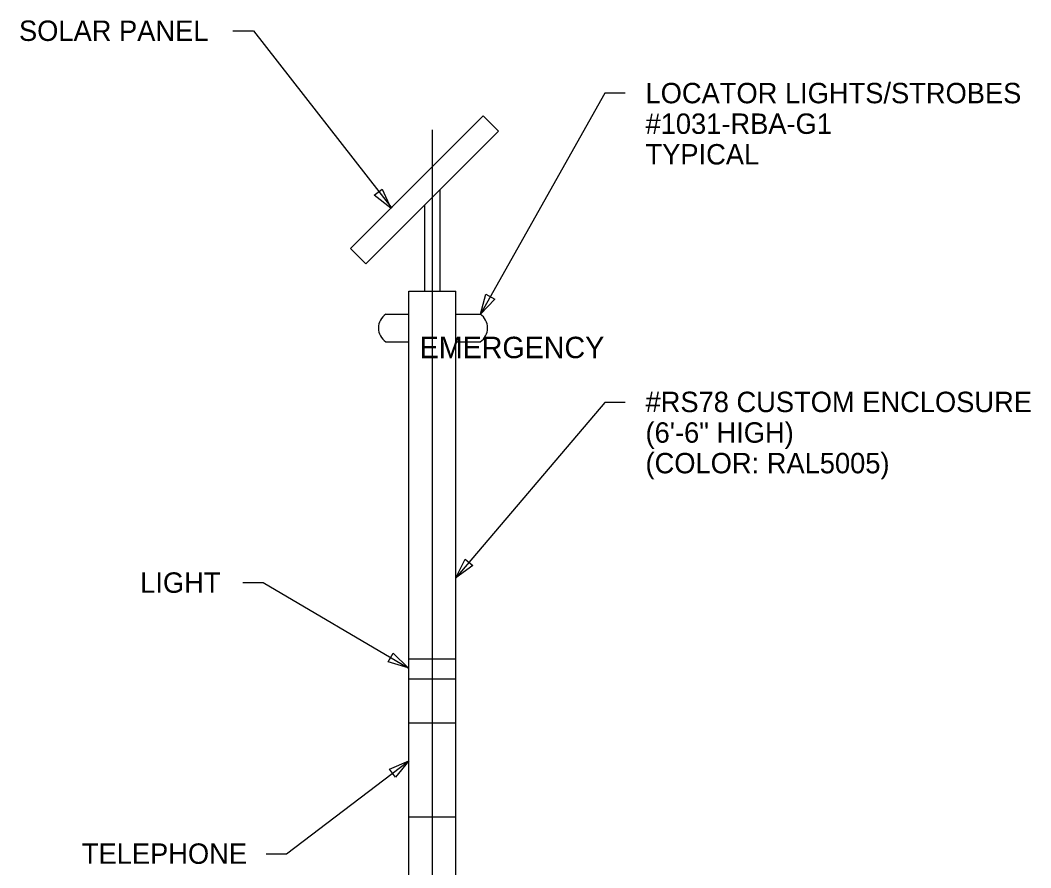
# Model space of a CAD drawing. Extents: x 10097.7 to 10174.5, y 10050.6 to 10139.4.
# Drawn here: x 10141.45 to 10174.48, y 10091.35 to 10119.05 of the extents above; entities that cross this region are included whole.
import ezdxf

# ---------------------------------------------------------------- set-up
doc = ezdxf.new("R2010")
doc.units = 0
for name, color, linetype in [('Level 61', 7, 'Continuous'), ('Level 62', 7, 'Continuous'), ('Level 63', 7, 'Continuous')]:
    doc.layers.add(name, color=color, linetype=linetype)

msp = doc.modelspace()

# ---------------------------------------------------------------- linework, layer by layer
at = {"layer": 'Level 61'}
for p, q in [((10154.912, 10115.461), (10154.912, 10077.777)), ((10155.167, 10113.512), (10155.167, 10110.189)), ((10154.657, 10113.001), (10154.657, 10110.189)), ((10154.144, 10110.189), (10155.68, 10110.189)), ((10154.144, 10079.512), (10154.144, 10110.189)), ((10155.68, 10079.512), (10155.68, 10110.189)), ((10154.144, 10098.177), (10155.68, 10098.177)), ((10154.144, 10097.526), (10155.68, 10097.526))]:
    msp.add_line(p, q, dxfattribs=at)
at = {"layer": 'Level 62'}
for p, q in [((10156.584, 10115.923), (10152.246, 10111.584)), ((10156.584, 10115.923), (10157.081, 10115.426)), ((10157.081, 10115.426), (10152.743, 10111.087)), ((10152.246, 10111.584), (10152.743, 10111.087)), ((10153.391, 10109.437), (10154.144, 10109.437)), ((10155.68, 10109.437), (10156.488, 10109.437)), ((10153.391, 10108.541), (10154.144, 10108.541)), ((10155.68, 10108.541), (10156.488, 10108.541)), ((10154.144, 10096.084), (10155.68, 10096.084)), ((10154.144, 10093.011), (10155.68, 10093.011))]:
    msp.add_line(p, q, dxfattribs=at)
for centre, start, end in [((10153.697, 10108.989), 123.8578, 236.1318), ((10156.182, 10108.989), 303.8682, 56.1422)]:
    msp.add_arc(centre, 0.542, start, end, dxfattribs=at)
at = {"layer": 'Level 63'}
for p, q in [((10148.401, 10118.703), (10149.067, 10118.703)), ((10149.067, 10118.703), (10153.595, 10112.902)), ((10160.553, 10116.658), (10156.488, 10109.437)), ((10161.219, 10116.658), (10160.553, 10116.658)), ((10160.553, 10106.556), (10155.68, 10100.825)), ((10161.219, 10106.556), (10160.553, 10106.556)), ((10148.722, 10100.67), (10149.389, 10100.67)), ((10149.389, 10100.67), (10154.131, 10097.883)), ((10150.153, 10091.811), (10154.144, 10094.85)), ((10149.486, 10091.811), (10150.153, 10091.811))]:
    msp.add_line(p, q, dxfattribs=at)
for points in [[(10153.281, 10113.53), (10153.559, 10112.902), (10153.018, 10113.325)], [(10156.96, 10109.936), (10156.488, 10109.437), (10156.67, 10110.1)], [(10156.239, 10101.225), (10155.68, 10100.825), (10155.985, 10101.441)], [(10153.641, 10098.364), (10154.131, 10097.883), (10153.472, 10098.077)], [(10153.512, 10094.579), (10154.144, 10094.85), (10153.714, 10094.314)]]:
    msp.add_lwpolyline(points, close=True, dxfattribs=at)

# ---------------------------------------------------------------- texts
at = {"layer": 'Level 62'}
msp.add_text('EMERGENCY', height=0.7, dxfattribs=at).set_placement((10154.504, 10108.003))
at = {"layer": 'Level 63'}
for s, height, p in [('SOLAR PANEL', 0.66667, (10141.405, 10118.369)), ('LOCATOR LIGHTS/STROBES', 0.66667, (10161.886, 10116.332)), ('#1031-RBA-G1', 0.66667, (10161.886, 10115.332)), ('TYPICAL', 0.6667, (10161.886, 10114.332)), ('#RS78 CUSTOM ENCLOSURE', 0.66667, (10161.886, 10106.241)), ('(6\'-6" HIGH)', 0.66667, (10161.886, 10105.241)), ('(COLOR: RAL5005)', 0.66667, (10161.886, 10104.241)), ('LIGHT', 0.6667, (10145.368, 10100.337)), ('TELEPHONE', 0.6667, (10143.46, 10091.481))]:
    msp.add_text(s, height=height, dxfattribs=at).set_placement(p)

doc.saveas('drawing.dxf')
